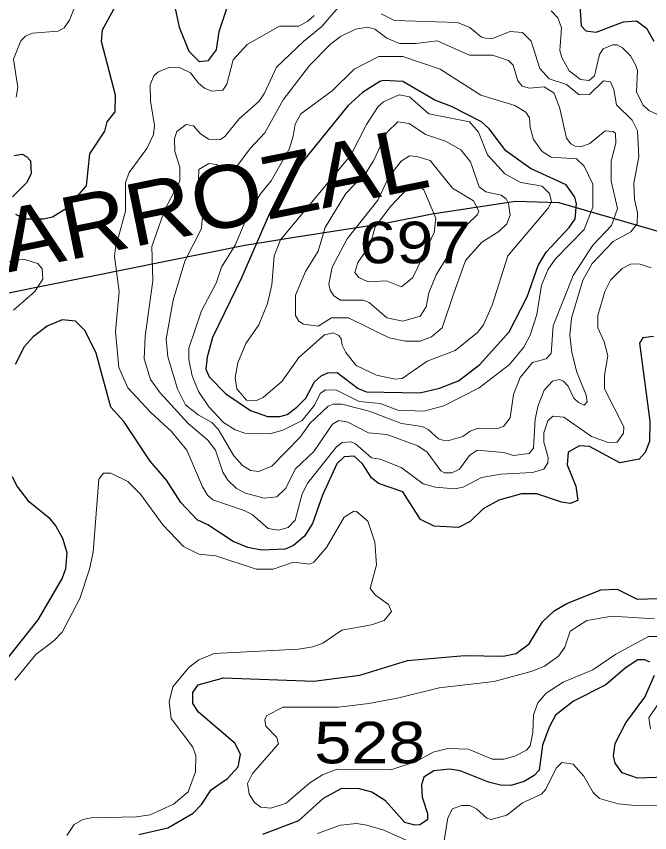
# Model space of a CAD drawing. Extents: x 577 to 602.9, y 7483.8 to 7511.6.
# Drawn here: x 598.63 to 599.849, y 7494.897 to 7496.468 of the extents above; entities that cross this region are included whole.
import ezdxf
from ezdxf.enums import TextEntityAlignment as Align

# ---------------------------------------------------------------- set-up
doc = ezdxf.new("R2010")
doc.units = 0
doc.header["$LTSCALE"] = 0.032
for name, color, linetype, lineweight in [('1', 7, 'Continuous', 25), ('2', 7, 'Continuous', 13), ('26', 7, 'Continuous', 25)]:
    doc.layers.add(name, color=color, linetype=linetype, lineweight=lineweight)
doc.layers.add('61', color=7, linetype='Continuous')

msp = doc.modelspace()

# ---------------------------------------------------------------- linework, layer by layer
at = {"layer": '1'}
for points in [[(598.6282, 7496.0875), (598.6457, 7496.0788), (598.6815, 7496.0788), (598.6998, 7496.0827), (598.7284, 7496.1002), (598.765, 7496.1424), (598.7714, 7496.2036), (598.8, 7496.2473), (598.8048, 7496.2656), (598.8199, 7496.2847), (598.8207, 7496.3165), (598.7936, 7496.4199), (598.796, 7496.4422), (598.8286, 7496.5026), (598.8533, 7496.5288), (598.874, 7496.5392), (598.8978, 7496.5384)], [(598.936, 7496.4835), (598.9431, 7496.4477), (598.9622, 7496.4016), (598.9821, 7496.3817), (598.9996, 7496.3833), (599.0155, 7496.404), (599.0203, 7496.439), (599.037, 7496.4891)], [(599.7145, 7496.4994), (599.7176, 7496.4501), (599.7264, 7496.4406), (599.7463, 7496.4382), (599.7987, 7496.4581), (599.8242, 7496.4596), (599.8433, 7496.4453), (599.8576, 7496.4207)], [(598.6259, 7496.2004), (598.641, 7496.2028), (598.6497, 7496.1988), (598.6569, 7496.1901), (598.6585, 7496.1654), (598.6497, 7496.1479), (598.6227, 7496.1209)], [(599.8568, 7495.8521), (599.8361, 7495.8497), (599.8298, 7495.8394), (599.8496, 7495.6891), (599.8488, 7495.6502), (599.8409, 7495.6287), (599.829, 7495.616), (599.7916, 7495.6088), (599.7335, 7495.6406), (599.7145, 7495.6414), (599.6922, 7495.6295), (599.6906, 7495.6048), (599.7073, 7495.5643), (599.7113, 7495.5365), (599.6962, 7495.5309), (599.6795, 7495.5333), (599.6318, 7495.5492), (599.6023, 7495.5492), (599.5586, 7495.5372), (599.5284, 7495.5205), (599.5037, 7495.4959), (599.4815, 7495.4848), (599.4346, 7495.4871), (599.4083, 7495.4999), (599.3741, 7495.5531), (599.3272, 7495.5691), (599.3137, 7495.5802), (599.2962, 7495.6072), (599.2803, 7495.6215), (599.2612, 7495.6207), (599.2469, 7495.6072), (599.2191, 7495.5468), (599.2, 7495.4919), (599.1849, 7495.4681), (599.1634, 7495.4498), (599.1475, 7495.4426), (599.1022, 7495.441), (599.0759, 7495.4458), (599.0473, 7495.4577), (598.9988, 7495.4895), (598.9781, 7495.4991), (598.9463, 7495.5325), (598.9193, 7495.5754), (598.8875, 7495.612), (598.8366, 7495.6883), (598.8119, 7495.7162), (598.7833, 7495.8203), (598.7626, 7495.8633), (598.7435, 7495.8816), (598.7181, 7495.8839), (598.6895, 7495.872), (598.6624, 7495.8513), (598.6449, 7495.8323), (598.6275, 7495.7981)], [(598.6219, 7495.5826), (598.6306, 7495.5643), (598.6521, 7495.5365), (598.6927, 7495.5038), (598.7062, 7495.4871), (598.7189, 7495.4641), (598.7268, 7495.4363), (598.7245, 7495.4052), (598.7181, 7495.387), (598.6712, 7495.3066), (598.5917, 7495.2072)], [(599.3829, 7495.2287), (599.4926, 7495.2383), (599.5674, 7495.2367), (599.592, 7495.2422), (599.6174, 7495.2605), (599.6429, 7495.3027), (599.6652, 7495.3241), (599.6898, 7495.3385), (599.755, 7495.3647), (599.7868, 7495.3655), (599.825, 7495.3464), (599.8647, 7495.348)], [(598.866, 7494.8939), (598.9217, 7494.9067), (598.9702, 7494.9345), (598.9861, 7494.9512), (599.0052, 7494.9798), (599.0362, 7495.0013), (599.0568, 7495.0236), (599.0616, 7495.0474), (599.0513, 7495.0689), (598.9805, 7495.1293), (598.9694, 7495.146), (598.9694, 7495.1667), (598.9797, 7495.1818), (599.029, 7495.1953), (599.2028, 7495.1887), (599.2914, 7495.2001), (599.3829, 7495.2287)], [(599.8496, 7495.2255), (599.8401, 7495.2295), (599.8266, 7495.2295), (599.8019, 7495.2136), (599.7646, 7495.1818), (599.7025, 7495.15), (599.6683, 7495.123), (599.6556, 7495.0999), (599.6429, 7495.0657), (599.6365, 7495.0172), (599.627, 7495.0069), (599.6079, 7494.9957), (599.5817, 7494.9878), (599.5618, 7494.9886), (599.5387, 7494.9941), (599.4847, 7495.0164), (599.4648, 7495.0196), (599.4338, 7495.0164), (599.4147, 7495.0037), (599.4099, 7494.9894), (599.4115, 7494.9655), (599.4218, 7494.9337), (599.4218, 7494.9218), (599.4067, 7494.9122), (599.3972, 7494.9114), (599.3781, 7494.917), (599.3407, 7494.9584), (599.3145, 7494.9751), (599.2882, 7494.9822), (599.2548, 7494.9814), (599.2207, 7494.9631), (599.1729, 7494.9202), (599.1038, 7494.8939)], [(599.8791, 7495.0037), (599.8258, 7495.0021), (599.7964, 7495.0124), (599.7828, 7495.0307), (599.7797, 7495.045), (599.7828, 7495.0689), (599.8035, 7495.1086), (599.8401, 7495.1579), (599.8584, 7495.2001)]]:
    msp.add_lwpolyline(points, dxfattribs=at)
msp.add_lwpolyline([(599.0335, 7495.742), (599.0805, 7495.7094), (599.1133, 7495.6979), (599.1372, 7495.6979), (599.1515, 7495.7018), (599.1698, 7495.7162), (599.1873, 7495.7337), (599.204, 7495.7647), (599.2167, 7495.7766), (599.2294, 7495.7822), (599.2477, 7495.783), (599.2882, 7495.7519), (599.3041, 7495.7456), (599.4067, 7495.744), (599.4449, 7495.7527), (599.4815, 7495.7671), (599.522, 7495.7981), (599.5785, 7495.8609), (599.6135, 7495.9285), (599.6349, 7495.9889), (599.65, 7496.0144), (599.6946, 7496.0621), (599.7057, 7496.0788), (599.7081, 7496.1074), (599.7049, 7496.1201), (599.6882, 7496.144), (599.6198, 7496.1758), (599.5721, 7496.2092), (599.5403, 7496.2521), (599.5252, 7496.2656), (599.468, 7496.295), (599.4354, 7496.307), (599.3741, 7496.3428), (599.336, 7496.3451), (599.3296, 7496.3428), (599.2962, 7496.3221), (599.2684, 7496.2958), (599.1833, 7496.1917), (599.1499, 7496.144), (599.1173, 7496.0891), (599.0632, 7495.9651), (599.0075, 7495.8505), (598.9972, 7495.8124), (598.9948, 7495.7893), (599.0012, 7495.7742)], close=True, dxfattribs=at)
at = {"layer": '2'}
for points in [[(598.6298, 7496.3125), (598.633, 7496.3316), (598.6243, 7496.3857), (598.6386, 7496.4215), (598.6473, 7496.4302), (598.6608, 7496.4358), (598.7102, 7496.4398), (598.7221, 7496.4461), (598.7324, 7496.4612), (598.7515, 7496.5105), (598.7833, 7496.5646), (598.8302, 7496.6052), (598.8565, 7496.6179), (598.9241, 7496.637), (598.9829, 7496.6728), (599.0107, 7496.6839), (599.0227, 7496.6839), (599.0346, 7496.6791), (599.0449, 7496.6664), (599.0449, 7496.6473), (599.0338, 7496.6187), (599.0354, 7496.6099), (599.0521, 7496.6036), (599.0815, 7496.606)], [(599.2572, 7496.4946), (599.2183, 7496.4485), (599.1825, 7496.4199), (599.1308, 7496.3706), (599.1077, 7496.3205), (599.0974, 7496.3054), (599.0592, 7496.2712), (599.0314, 7496.237), (599.0227, 7496.2314), (598.9996, 7496.2322), (598.9837, 7496.2426), (598.971, 7496.2577)], [(599.2032, 7496.47), (599.1912, 7496.4589), (599.1737, 7496.4493), (599.1364, 7496.4493), (599.0743, 7496.4143), (599.0473, 7496.3849), (599.0354, 7496.338), (599.0274, 7496.3261), (599.006, 7496.3245), (598.9924, 7496.33), (598.9805, 7496.3396), (598.9654, 7496.3595), (598.9455, 7496.369), (598.9233, 7496.3698), (598.9026, 7496.361), (598.8946, 7496.3539), (598.8875, 7496.3364), (598.8883, 7496.3054), (598.8962, 7496.2585), (598.8938, 7496.241), (598.8811, 7496.2139), (598.8469, 7496.1678), (598.8398, 7496.1487), (598.8398, 7496.0931), (598.8207, 7496.0231), (598.8191, 7496.0064), (598.8278, 7495.9388), (598.8207, 7495.8617), (598.827, 7495.7925), (598.8445, 7495.7535), (598.8891, 7495.7058), (598.9288, 7495.6692), (598.9582, 7495.6335), (598.9885, 7495.5627), (598.998, 7495.5468), (599.0083, 7495.538), (599.0688, 7495.5174), (599.0839, 7495.5094), (599.1149, 7495.4824), (599.1348, 7495.4792), (599.1531, 7495.4848), (599.1666, 7495.4983), (599.1801, 7495.5492), (599.1912, 7495.5706), (599.2461, 7495.6398)], [(598.9344, 7496.233), (598.9352, 7496.2084), (598.9447, 7496.1782), (598.9447, 7496.1511), (598.9161, 7496.0963), (598.8907, 7496.0255), (598.893, 7495.9595), (598.8779, 7495.8529), (598.8763, 7495.8092), (598.8883, 7495.7694), (598.9066, 7495.744), (598.9606, 7495.6844), (598.9988, 7495.6525), (599.0131, 7495.6335), (599.0274, 7495.5913), (599.037, 7495.5754), (599.0537, 7495.5595), (599.0712, 7495.5508), (599.1069, 7495.5412), (599.1316, 7495.5436), (599.1483, 7495.5595), (599.1674, 7495.5977), (599.2024, 7495.6311), (599.2389, 7495.6836), (599.2509, 7495.6907), (599.2684, 7495.6875), (599.3081, 7495.6669), (599.3431, 7495.6637), (599.4027, 7495.6414), (599.421, 7495.6295), (599.4473, 7495.5937), (599.4544, 7495.5897), (599.4687, 7495.5897), (599.4831, 7495.5969), (599.5021, 7495.6231), (599.5173, 7495.6335), (599.5681, 7495.6287), (599.5872, 7495.6231), (599.6174, 7495.6271), (599.6254, 7495.6374), (599.6286, 7495.6931), (599.6349, 7495.7193), (599.6461, 7495.7488), (599.662, 7495.7663), (599.6755, 7495.7694), (599.6834, 7495.7663), (599.6922, 7495.7567), (599.7033, 7495.7337), (599.7121, 7495.7249), (599.7232, 7495.7201), (599.7288, 7495.7265), (599.7272, 7495.7392), (599.7089, 7495.7838), (599.6993, 7495.8211), (599.6954, 7495.8545), (599.6986, 7495.8871), (599.7208, 7495.9603), (599.7383, 7495.9929), (599.7789, 7496.035), (599.8131, 7496.0533), (599.825, 7496.0692), (599.8258, 7496.0907), (599.8202, 7496.1161), (599.8186, 7496.1471), (599.8282, 7496.198), (599.8258, 7496.2481), (599.8154, 7496.2688), (599.7852, 7496.2982), (599.7805, 7496.3277), (599.7741, 7496.342), (599.7606, 7496.3443), (599.7335, 7496.3181), (599.7137, 7496.3173), (599.689, 7496.3372), (599.6556, 7496.3483), (599.6381, 7496.3682), (599.6214, 7496.4207), (599.6047, 7496.4374), (599.5809, 7496.439), (599.5467, 7496.4255), (599.5332, 7496.4263), (599.5252, 7496.4286), (599.5029, 7496.4469), (599.4791, 7496.4565), (599.3582, 7496.4604), (599.332, 7496.4732)], [(599.8655, 7496.2791), (599.848, 7496.2871), (599.8361, 7496.2982), (599.8242, 7496.3229), (599.8258, 7496.3642), (599.8226, 7496.3738), (599.8123, 7496.3921), (599.7972, 7496.408), (599.7868, 7496.4135), (599.7781, 7496.4135), (599.7598, 7496.4056), (599.7526, 7496.3952), (599.7431, 7496.3539), (599.7327, 7496.3451), (599.716, 7496.3467), (599.6946, 7496.3634), (599.6803, 7496.3889), (599.6763, 7496.4024), (599.6795, 7496.4461), (599.6723, 7496.4652), (599.6596, 7496.4787)], [(598.971, 7496.2577), (598.9567, 7496.2601), (598.9392, 7496.2465), (598.9344, 7496.233)], [(598.5996, 7495.9937), (598.6434, 7496.0008), (598.6712, 7495.9929), (598.6799, 7495.9825), (598.6807, 7495.9627), (598.6656, 7495.9388), (598.6243, 7495.903)], [(599.2461, 7495.6398), (599.2572, 7495.6478), (599.2747, 7495.6494), (599.2827, 7495.6454), (599.3137, 7495.6184), (599.3304, 7495.616), (599.3709, 7495.6001), (599.4131, 7495.5683), (599.4369, 7495.5619), (599.4735, 7495.5587), (599.4902, 7495.5619), (599.5252, 7495.581), (599.5626, 7495.5873), (599.6238, 7495.5905), (599.6453, 7495.5969), (599.6532, 7495.6088), (599.654, 7495.6191), (599.6453, 7495.6486), (599.6453, 7495.6669), (599.6532, 7495.6899), (599.6628, 7495.6987), (599.6842, 7495.6971), (599.7375, 7495.6597), (599.7693, 7495.6478), (599.7868, 7495.6486), (599.7987, 7495.6661), (599.7995, 7495.678), (599.7622, 7495.7511), (599.7622, 7495.7774), (599.7685, 7495.8148), (599.7614, 7495.8418), (599.7494, 7495.8688), (599.7494, 7495.8927), (599.763, 7495.9388), (599.7741, 7495.9603), (599.7964, 7495.9833), (599.8123, 7495.9913), (599.829, 7495.9921), (599.852, 7495.9841)], [(599.1729, 7495.2502), (599.2008, 7495.255), (599.2199, 7495.2621), (599.2564, 7495.2868), (599.3137, 7495.2971), (599.3383, 7495.3058), (599.3519, 7495.3225), (599.3463, 7495.3361), (599.3216, 7495.3544), (599.3113, 7495.3671), (599.3232, 7495.4124), (599.3201, 7495.4561), (599.3065, 7495.4967), (599.2851, 7495.515), (599.2795, 7495.5158), (599.2612, 7495.5046), (599.227, 7495.4458), (599.2024, 7495.418), (599.1944, 7495.414), (599.1634, 7495.418), (599.1244, 7495.4045), (599.0918, 7495.4045), (599.0139, 7495.4299), (598.9813, 7495.4331), (598.9519, 7495.4482), (598.9121, 7495.4895), (598.8692, 7495.5484), (598.8445, 7495.573), (598.8119, 7495.5889), (598.7976, 7495.5889), (598.7889, 7495.5778), (598.7777, 7495.4371), (598.771, 7495.4042), (598.7523, 7495.348), (598.7181, 7495.2828), (598.703, 7495.2669), (598.6672, 7495.2398), (598.6267, 7495.1905)], [(599.8584, 7495.309), (599.7765, 7495.3138), (599.728, 7495.3058), (599.6962, 7495.2852), (599.6858, 7495.2542), (599.6739, 7495.2367), (599.6469, 7495.2176), (599.623, 7495.208), (599.5499, 7495.1882), (599.4441, 7495.1762), (599.3662, 7495.1564), (599.3086, 7495.146), (599.25, 7495.1388), (599.1427, 7495.1389), (599.1117, 7495.1222), (599.1085, 7495.1142), (599.1101, 7495.1023), (599.1316, 7495.08), (599.1348, 7495.0681), (599.0847, 7495.0108), (599.0751, 7494.9918), (599.0783, 7494.9711), (599.0887, 7494.9552), (599.1006, 7494.9464), (599.1197, 7494.944), (599.1491, 7494.9536), (599.1952, 7494.9933), (599.2191, 7495.0085), (599.2477, 7495.0196), (599.3511, 7495.018)], [(599.3511, 7495.018), (599.3996, 7495.0339), (599.4322, 7495.0522), (599.4608, 7495.0593), (599.5006, 7495.0578), (599.5459, 7495.0387), (599.5689, 7495.0387), (599.5912, 7495.045), (599.6119, 7495.0562), (599.619, 7495.0641), (599.6246, 7495.0896), (599.6254, 7495.1238), (599.6341, 7495.1468), (599.65, 7495.1659), (599.6827, 7495.1866), (599.7399, 7495.2104), (599.7844, 7495.2406), (599.8473, 7495.2748), (599.8663, 7495.2748)], [(598.7268, 7494.8916), (598.7412, 7494.913), (598.7579, 7494.9226), (598.7738, 7494.9258), (598.8612, 7494.9273), (598.8875, 7494.9313), (598.9328, 7494.952), (598.9606, 7494.9759), (598.9749, 7495.014), (598.9757, 7495.045), (598.9694, 7495.0617), (598.928, 7495.1166), (598.9241, 7495.1492), (598.9312, 7495.1778), (598.9622, 7495.2152), (598.9813, 7495.2295), (599.0107, 7495.2422), (599.1729, 7495.2502)], [(599.864, 7495.142), (599.848, 7495.1182), (599.8512, 7495.0967)], [(599.8655, 7494.9488), (599.821, 7494.9496), (599.7884, 7494.9528), (599.7526, 7494.9631), (599.7407, 7494.9743), (599.7224, 7495.0061), (599.7017, 7495.0291), (599.6803, 7495.0323), (599.6691, 7495.0212), (599.6493, 7494.9806), (599.6413, 7494.9711), (599.6047, 7494.9544), (599.5745, 7494.9305), (599.5443, 7494.9226), (599.5355, 7494.925), (599.5157, 7494.9432), (599.5029, 7494.9496), (599.487, 7494.9496), (599.4695, 7494.9432), (599.4608, 7494.9258), (599.4536, 7494.882)], [(599.4091, 7494.8701), (599.3375, 7494.9019), (599.3049, 7494.9114), (599.2851, 7494.9146), (599.2541, 7494.9114), (599.2095, 7494.8955)]]:
    msp.add_lwpolyline(points, dxfattribs=at)
for points in [[(598.9863, 7496.1289), (598.9916, 7496.0835), (598.9877, 7496.078), (598.9861, 7496.0597), (598.9543, 7495.9969), (598.932, 7495.9221), (598.9185, 7495.8474), (598.9217, 7495.8132), (598.94, 7495.7511), (598.9559, 7495.7209), (598.9797, 7495.7011), (599.006, 7495.6867), (599.0187, 7495.674), (599.0489, 7495.6223), (599.0656, 7495.604), (599.0807, 7495.5945), (599.0966, 7495.5921), (599.1221, 7495.6025), (599.1761, 7495.6581), (599.1952, 7495.6844), (599.2302, 7495.7178), (599.2397, 7495.7217), (599.2564, 7495.7217), (599.3089, 7495.7082), (599.3717, 7495.6844), (599.4115, 7495.6788), (599.4226, 7495.6732), (599.4425, 7495.6549), (599.4513, 7495.6525), (599.4624, 7495.6518), (599.4894, 7495.6597), (599.5037, 7495.67), (599.5188, 7495.6756), (599.5562, 7495.6748), (599.5681, 7495.6788), (599.5809, 7495.6955), (599.5872, 7495.7408), (599.6, 7495.7734), (599.6238, 7495.802), (599.65, 7495.8092), (599.6596, 7495.8195), (599.6636, 7495.8728), (599.7017, 7495.9698), (599.7399, 7496.0279), (599.7757, 7496.066), (599.7876, 7496.0986), (599.7749, 7496.1511), (599.7749, 7496.1893), (599.7844, 7496.2243), (599.7836, 7496.2426), (599.7789, 7496.2465), (599.7638, 7496.2481), (599.7343, 7496.2235), (599.7168, 7496.2171), (599.7057, 7496.2187), (599.6978, 7496.2227), (599.689, 7496.2338), (599.6763, 7496.2911), (599.6652, 7496.3205), (599.6461, 7496.3324), (599.6182, 7496.33), (599.6039, 7496.334), (599.5952, 7496.3443), (599.5864, 7496.3746), (599.5777, 7496.3833), (599.5467, 7496.3937), (599.5021, 7496.3937), (599.4401, 7496.4215), (599.3988, 7496.4159), (599.3678, 7496.4159), (599.3431, 7496.4263), (599.3201, 7496.4437), (599.3065, 7496.4477), (599.2827, 7496.4437), (599.2541, 7496.4294), (599.235, 7496.4151), (599.1944, 7496.3738), (599.1435, 7496.3078), (599.1085, 7496.2442), (599.0799, 7496.2139), (599.0537, 7496.179), (599.0457, 7496.1742), (599.0306, 7496.1742), (599.0155, 7496.1829), (599.0004, 7496.1853), (598.9813, 7496.1734), (598.9797, 7496.1384)], [(599.1626, 7496.2378), (599.1554, 7496.2124), (599.1205, 7496.1519), (599.0998, 7496.1265), (599.0775, 7496.0899), (599.0513, 7496.0279), (599.025, 7495.9857), (599.0147, 7495.9547), (598.9861, 7495.9014), (598.9622, 7495.8299), (598.9622, 7495.8076), (598.9686, 7495.7766), (598.9805, 7495.7464), (599.0004, 7495.717), (599.029, 7495.6867), (599.0513, 7495.6724), (599.0696, 7495.6661), (599.1181, 7495.6645), (599.1427, 7495.6716), (599.1801, 7495.6907), (599.204, 7495.7201), (599.2151, 7495.7424), (599.2254, 7495.7496), (599.2461, 7495.7488), (599.2898, 7495.7273), (599.3304, 7495.7233), (599.3646, 7495.7106), (599.4147, 7495.7082), (599.4528, 7495.7185), (599.5212, 7495.7535), (599.5793, 7495.7981), (599.6071, 7495.8315), (599.619, 7495.8545), (599.6318, 7495.8943), (599.6413, 7495.9507), (599.654, 7495.9817), (599.6683, 7496.0016), (599.7232, 7496.0581), (599.7399, 7496.101), (599.7399, 7496.1456), (599.7232, 7496.1797), (599.7081, 7496.1941), (599.6596, 7496.1972), (599.6421, 7496.2084), (599.6254, 7496.2314), (599.619, 7496.2545), (599.6182, 7496.2728), (599.6111, 7496.2839), (599.5896, 7496.2966), (599.5244, 7496.3165), (599.4457, 7496.3666), (599.3741, 7496.3913), (599.328, 7496.3913), (599.2803, 7496.3666), (599.2381, 7496.3253), (599.1777, 7496.2807), (599.1666, 7496.2609)], [(599.2556, 7495.8474), (599.2505, 7495.8539), (599.2397, 7495.8593), (599.223, 7495.8553), (599.1737, 7495.8116), (599.1419, 7495.7663), (599.1054, 7495.7344), (599.091, 7495.7281), (599.0731, 7495.7294), (599.0545, 7495.7511), (599.0513, 7495.7726), (599.0561, 7495.8012), (599.072, 7495.8386), (599.0966, 7495.8744), (599.1133, 7495.9157), (599.1221, 7495.9515), (599.126, 7496.0072), (599.1388, 7496.0382), (599.2739, 7496.2012), (599.3041, 7496.2601), (599.3264, 7496.295), (599.3367, 7496.3038), (599.367, 7496.3173), (599.3868, 7496.3133), (599.4242, 7496.2807), (599.5021, 7496.2656), (599.5196, 7496.2457), (599.5371, 7496.202), (599.5705, 7496.1654), (599.6015, 7496.1487), (599.6421, 7496.1416), (599.6564, 7496.1273), (599.6604, 7496.1114), (599.654, 7496.0994), (599.5761, 7496.0072), (599.5459, 7495.9126), (599.5292, 7495.8744), (599.518, 7495.8601), (599.4751, 7495.8251), (599.421, 7495.8044), (599.3725, 7495.771), (599.359, 7495.7702), (599.3232, 7495.7774), (599.2843, 7495.7965), (599.2644, 7495.8211), (599.2572, 7495.8354)], [(599.4718, 7495.9337), (599.495, 7495.9984), (599.526, 7496.0334), (599.5586, 7496.0541), (599.5745, 7496.0692), (599.5809, 7496.0859), (599.5777, 7496.1082), (599.5729, 7496.1169), (599.5634, 7496.1241), (599.534, 7496.1304), (599.5212, 7496.14), (599.5045, 7496.1885), (599.4854, 7496.2116), (599.456, 7496.2283), (599.4179, 7496.241), (599.3861, 7496.2624), (599.3646, 7496.2656), (599.3431, 7496.245), (599.3177, 7496.1901), (599.3034, 7496.1678), (599.2644, 7496.1273), (599.2246, 7496.0621), (599.2111, 7496.0167), (599.1865, 7495.977), (599.1674, 7495.9317), (599.1674, 7495.8927), (599.1737, 7495.8816), (599.1825, 7495.876), (599.2111, 7495.872), (599.2366, 7495.8879), (599.2692, 7495.8879), (599.3479, 7495.8497), (599.3789, 7495.8434), (599.4075, 7495.8434), (599.429, 7495.8513), (599.4497, 7495.8688)], [(599.4385, 7495.9706), (599.4974, 7496.0668), (599.518, 7496.0867), (599.5204, 7496.0931), (599.5101, 7496.113), (599.4695, 7496.1376), (599.4266, 7496.1909), (599.4012, 7496.1988), (599.3868, 7496.1996), (599.3709, 7496.1893), (599.3463, 7496.1583), (599.3256, 7496.1145), (599.2668, 7496.0398), (599.2381, 7495.9857), (599.2318, 7495.9531), (599.2342, 7495.9412), (599.2413, 7495.9301), (599.2541, 7495.9221), (599.2978, 7495.9221), (599.3089, 7495.9173), (599.3431, 7495.8879), (599.3741, 7495.8816), (599.4075, 7495.8911), (599.4187, 7495.9094), (599.4242, 7495.9364)], [(599.3503, 7496.1026), (599.3837, 7496.1376), (599.4075, 7496.14), (599.4147, 7496.1344), (599.4377, 7496.0796), (599.4346, 7496.0525), (599.398, 7495.9746), (599.3924, 7495.9651), (599.3717, 7495.9476), (599.3423, 7495.9595), (599.3073, 7495.9571), (599.289, 7495.9658), (599.2819, 7495.9754), (599.2874, 7495.9945), (599.3113, 7496.0287), (599.3208, 7496.0629)]]:
    msp.add_lwpolyline(points, close=True, dxfattribs=at)
at = {"layer": '26'}
msp.add_lwpolyline([(596.3235, 7494.8199), (596.4766, 7494.8992), (596.554, 7494.9298), (596.7174, 7494.964), (596.8084, 7494.9933), (597.6244, 7495.7246), (597.6816, 7495.7502), (597.9299, 7495.7984), (599.0697, 7496.0277), (599.1695, 7496.044), (599.3435, 7496.0707), (599.4306, 7496.0881), (599.5907, 7496.1124), (599.6743, 7496.1101), (599.8741, 7496.052), (600.0689, 7495.9566), (600.1375, 7495.9162), (600.3027, 7495.8544), (600.3968, 7495.841), (600.5616, 7495.8366), (600.6496, 7495.8454)], dxfattribs=at)

# ---------------------------------------------------------------- texts
at = {"layer": '26', "width": 1.1}
msp.add_text('SERRA DO ARROZAL', height=0.12, rotation=11.483, dxfattribs=at).set_placement((598.5465, 7495.9615), align=Align.CENTER)
at = {"layer": '61', "width": 1.2}
for s, p in [('697', (599.3975, 7495.9931)), ('528', (599.3107, 7495.0305))]:
    msp.add_text(s, height=0.08, dxfattribs=at).set_placement(p, align=Align.CENTER)

doc.saveas('drawing.dxf')
